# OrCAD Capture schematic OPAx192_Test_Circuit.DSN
size A; title: OPAx192 36-V, Precision, Rail-to-Rail Input/Output, Low Offset; rev: 1.7; note: Datasheet: SBOS620E  EVM: N/A
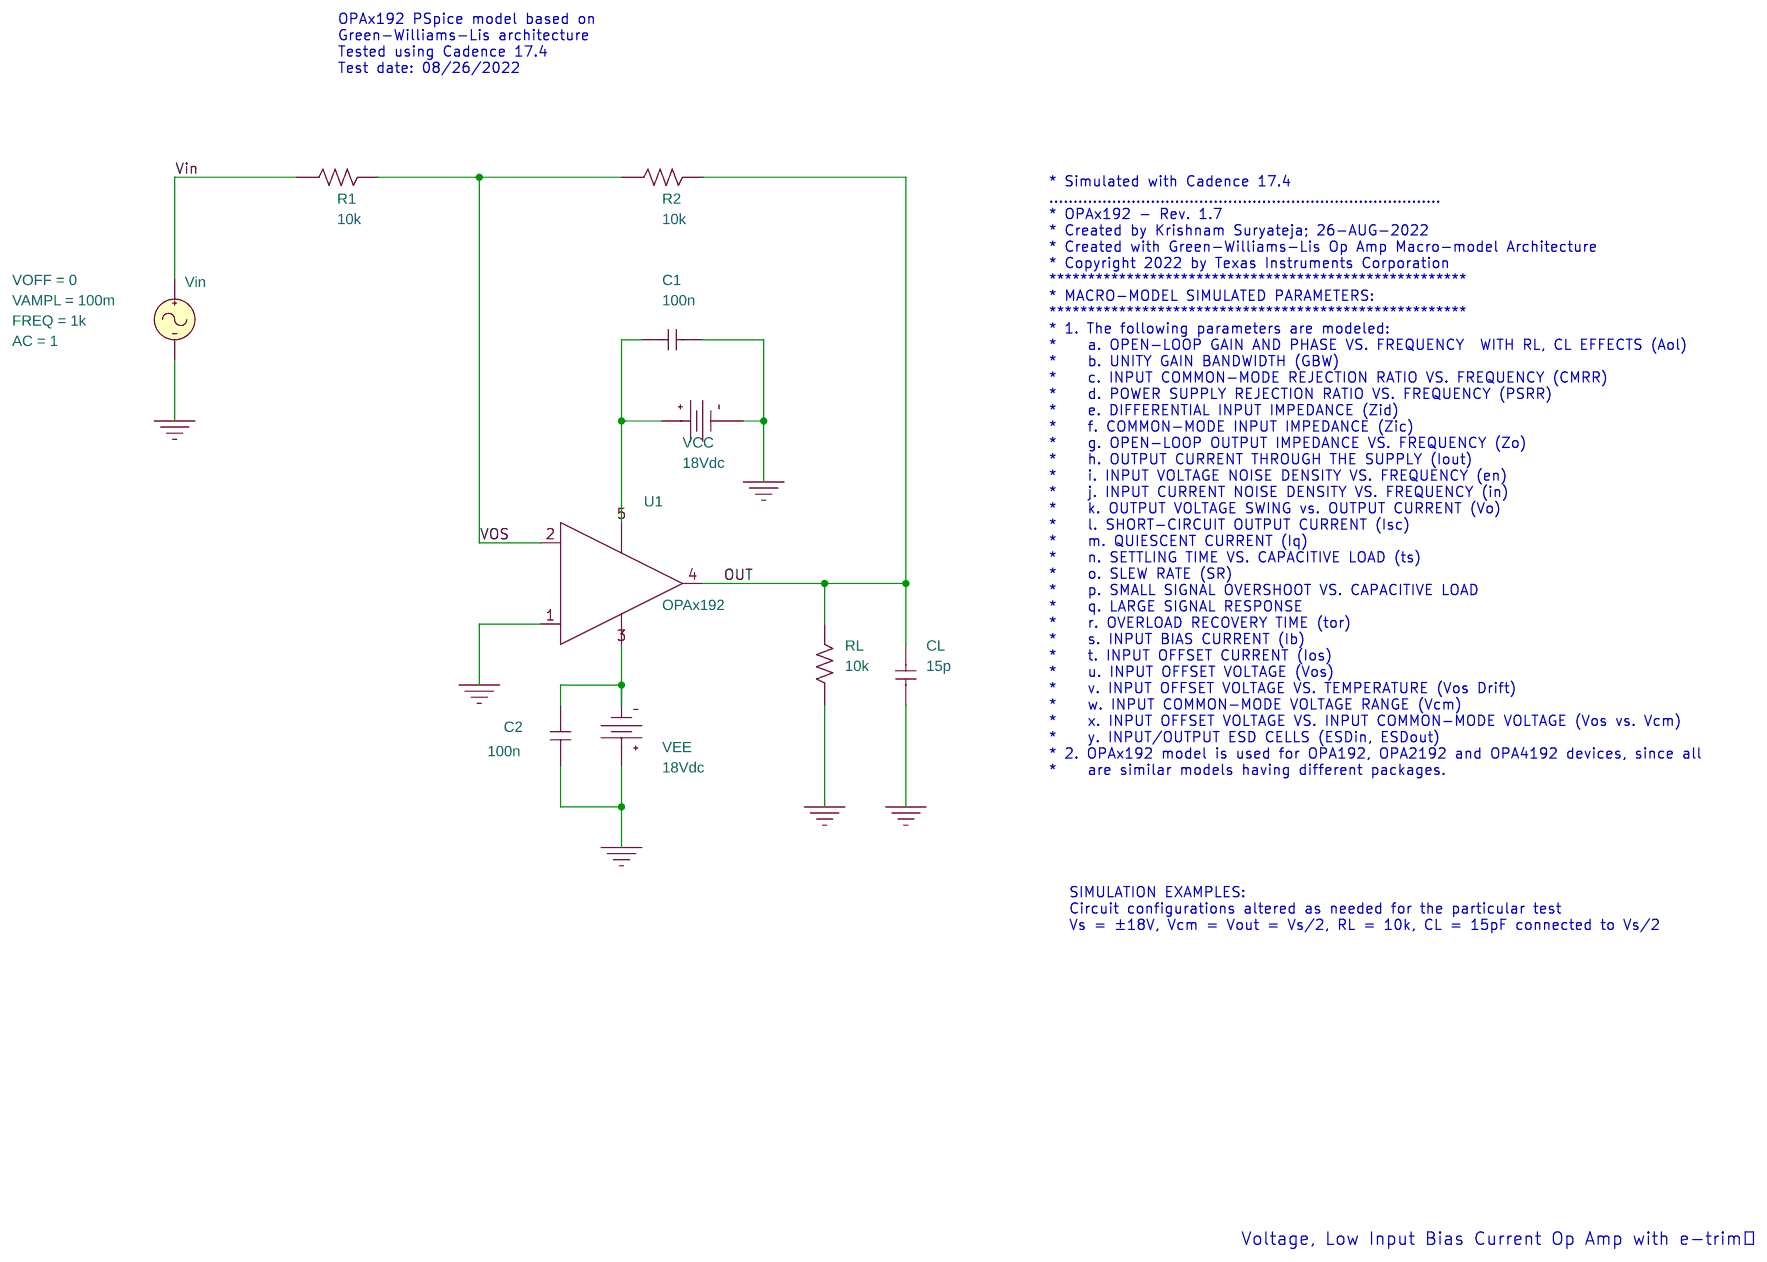
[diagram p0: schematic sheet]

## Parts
C1  100n  [cap196]
C2  100n  [cap196]
CL  15p  [RAD/CK05]
R1  10k  [AXRC05]
R2  10k  [AXRC05]
RL  10k  [AX/RC05]
U1  OPAx192
VCC  VDC
VEE  VDC
Vin  VSIN

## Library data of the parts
C1 C2 CL = C
R1 R2 RL = R
U1 = OPAx192
VCC VEE = VDC: DC: 18Vdc
Vin = VSIN: AC: 1; FREQ: 1k; VAMPL: 100m; VOFF: 0

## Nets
Vin: R1.1 Vin.1(+)
0: C1.2 C2.1 CL.1 RL.1 U1.1(+) VCC.1(-) VEE.0(+) Vin.2(-)
OUT: CL.2 R2.2 RL.2 U1.4(OUT)
VOS: R1.2 R2.1 U1.2(-)
N27303: C1.1 U1.5(V+) VCC.0(+)
N27354: C2.2 U1.3(V-) VEE.1(-)

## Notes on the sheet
- OPAx192 PSpice model based on
  Green-Williams-Lis architecture
  Tested using Cadence 17.4
  Test date: 08/26/2022
- * Simulated with Cadence 17.4
  .................................................................................
  * OPAx192 - Rev. 1.7
  * Created by Krishnam Suryateja; 26-AUG-2022
  * Created with Green-Williams-Lis Op Amp Macro-model Architecture
  * Copyright 2022 by Texas Instruments Corporation
  ******************************************************
  * MACRO-MODEL SIMULATED PARAMETERS:
  ******************************************************
  * 1. The following parameters are modeled:
  *    a. OPEN-LOOP GAIN AND PHASE VS. FREQUENCY  WITH RL, CL EFFECTS (Aol)
  *    b. UNITY GAIN BANDWIDTH (GBW)
  *    c. INPUT COMMON-MODE REJECTION RATIO VS. FREQUENCY (CMRR)
  *    d. POWER SUPPLY REJECTION RATIO VS. FREQUENCY (PSRR)
  *    e. DIFFERENTIAL INPUT IMPEDANCE (Zid)
  *    f. COMMON-MODE INPUT IMPEDANCE (Zic)
  *    g. OPEN-LOOP OUTPUT IMPEDANCE VS. FREQUENCY (Zo)
  *    h. OUTPUT CURRENT THROUGH THE SUPPLY (Iout)
  *    i. INPUT VOLTAGE NOISE DENSITY VS. FREQUENCY (en)
  *    j. INPUT CURRENT NOISE DENSITY VS. FREQUENCY (in)
  *    k. OUTPUT VOLTAGE SWING vs. OUTPUT CURRENT (Vo)
  *    l. SHORT-CIRCUIT OUTPUT CURRENT (Isc)
  *    m. QUIESCENT CURRENT (Iq)
  *    n. SETTLING TIME VS. CAPACITIVE LOAD (ts)
  *    o. SLEW RATE (SR)
  *    p. SMALL SIGNAL OVERSHOOT VS. CAPACITIVE LOAD
  *    q. LARGE SIGNAL RESPONSE
  *    r. OVERLOAD RECOVERY TIME (tor)
  *    s. INPUT BIAS CURRENT (Ib)
  *    t. INPUT OFFSET CURRENT (Ios)
  *    u. INPUT OFFSET VOLTAGE (Vos)
  *    v. INPUT OFFSET VOLTAGE VS. TEMPERATURE (Vos Drift)
  *    w. INPUT COMMON-MODE VOLTAGE RANGE (Vcm)
  *    x. INPUT OFFSET VOLTAGE VS. INPUT COMMON-MODE VOLTAGE (Vos vs. Vcm)
  *    y. INPUT/OUTPUT ESD CELLS (ESDin, ESDout)
  * 2. OPAx192 model is used for OPA192, OPA2192 and OPA4192 devices, since all
  *    are similar models having different packages.
- SIMULATION EXAMPLES:
  Circuit configurations altered as needed for the particular test
  Vs = ±18V, Vcm = Vout = Vs/2, RL = 10k, CL = 15pF connected to Vs/2
- Voltage, Low Input Bias Current Op Amp with e-trim™
